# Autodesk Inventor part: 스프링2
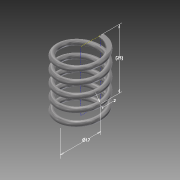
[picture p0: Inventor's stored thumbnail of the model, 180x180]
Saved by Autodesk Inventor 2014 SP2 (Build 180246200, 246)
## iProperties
Created: 2016-03
Part Number: 스프링2
Material: 스테인레스 스틸
Document SubType Name: Modeling
Designer: apexhp001
Density: 8.08 g/cm^3
Appearance: 반연마
Mass: 6.61453 g
Surface Area: 16.6961 cm^2
Volume: 0.81863 cm^3
Author: apexhp001
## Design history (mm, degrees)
sketch "스케치1"
  geometry: L1 (0, 0)-(8.5, 0); L2 (8.5, 0)-(8.5, 17.5); L3 (8.5, 17.5)-(0, 17.5); L4 (0, 17.5)-(0, 0); C1 r 1 at (8.5, 0)
  constraints: 8 end point, 2 parallel, 1 centre point, 1 coincident, 1 horizontal, 1 perpendicular
  dimensions: "d0" = 17.5 distance of L1.end L2.end (derived); "d1" = 17 diameter of L1.end L4; "d2" = 2 diameter of C1
feature "코일1" sketch "스케치1" pitch "d3" = 10; turns "d5" = 5; dims "d4" = 17.5 (= d0), "d6" = 0, angle "d7" = 90 deg, angle "d8" = 90 deg, "d9" = 0, "d10" = 0
sketch "스케치2"
  geometry: L1 (0, 9.5)-(0, 7.5) reference; 1 further point
  constraints: 1 vertical alignment
extrude "돌출1" cut sketch "스케치2" distance "d11" = 10; taper "d12" = 0 deg
node "작업 평면1"
sketch "스케치3"
  geometry: L1 (0, 7.5)-(0, 9.5) reference; 1 further point
  constraints: 1 vertical alignment
extrude "돌출2" cut sketch "스케치3" distance "d14" = 10; taper "d15" = 0 deg
node "솔리드1"
node "절단 모서리 투영1"
node "절단 모서리 투영2"
other parameters: "d13" = 17.5 (= d0)
